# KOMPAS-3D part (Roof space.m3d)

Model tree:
1. Plane XY
2. Plane ZX
3. Plane ZY
4. X Axis
5. Y Axis
6. Z Axis
7. Origin
8. Sketch:1
9. Extrude:1
     Wall Thickness 1 = 1; Wall Thickness 2 = 1; Distance 1 = 3000; Distance 2 = 160

Referenced files in D:\Documents and Settings\kashirsky\Рабочий стол\Seminar\: Cottage.a3d
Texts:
  Steel DIN 17102
  Three Point Plane
  Plane at Angle
  Line and Point Plane
  Axis through Two Vertices
  Axis of Feature
  Axis of Conical Surface
  Axis through Edge
  Trim by Surface
  Trim by Sketch
  Feature with No History
  Intersection Axis of Two Planes
  Two Line Plane
  Line and Face Plane
  Bend by line
  Hole in sheet body
  Cut in sheet body
  Point in CM
  Linear Dimension from Line to Point
  Surface Finish Symbol
  Geometric Tolerance Symbol
  Leader #1
  Leader #2
  Leader #3
  Shape Deviations and Datum
  Node point number
  Mark of coordination axis
  Node point designation
  Mark/Reference designation with leader
  Mark/reference designation on line
  Mark/Reference designation without leader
